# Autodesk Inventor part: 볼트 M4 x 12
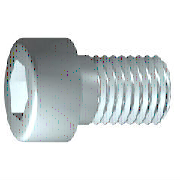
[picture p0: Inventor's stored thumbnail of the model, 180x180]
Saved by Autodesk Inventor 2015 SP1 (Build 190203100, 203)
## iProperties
IsCustomPart: 0
Created: 2012-02
Part Number: 볼트 M4 x 12
Material: 스테인리스강
Description: 6각 소켓 머리 캡 나사
Document SubType Name: Modeling
Standard: ISO 4762
Designer: mduedu
Standard Revision: Fourth edition 2004-03-01
Standards Organization: ISO
Language: ko-KR
Size Designation: M4 x 12
Categories: <MemberInstance><Categories><Category DisplayName="조임쇠" InternalName="e4da775c-781d-43d5-af7c-5136215cf5a6" Mnemonic="FSTN"><Category DisplayName="볼트" InternalN
Density: 8.08 g/cm^3
Appearance: 반광택
Author: mduedu
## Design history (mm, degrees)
sketch "스케치1"
  geometry: L1 (-1, 0)-(12, 0); L2 (12, 0)-(12, 2); L3 (12, 2)-(1.75, 2); L4 (1.75, 2)-(1.32, 2); L5 (1.32, 2)-(0, 2); L6 (0, 2)-(0, 3.5); L7 (0, 3.5)-(-4, 3.5); L8 (-4, 3.5)-(-4, 1.732); L9 (-4, 1.732)-(-2, 1.732); L10 (-2, 1.732)-(-1, 0); L11 (-7.2, 0)-(15.2, 0) reference; L12 (0, -0.7)-(0, 4.2) reference; L13 (1.75, 2)-(0, 2)
  constraints: 22 end point, 6 parallel, 2 collinear, 2 perpendicular, 1 horizontal, 1 point on line
  dimensions: "d1" = 10.25 distance from line of L3.end L2 (= GEL); "d2" = 0.42952 distance of L4.end L3.end (computed from GAL); "d3" = 4 distance between parallel lines of L8 L6 (= KOH); "d4" = 2 distance of L8.end L9.end (= INTI); "d5" = 60 deg angle of L10 L1; "d6" = 4 diameter of L3 L1 (= GD); "d7" = 4 diameter of L5 L1 (= BDM); "d8" = 3.4641 diameter of L9 L1 (= 1.1547 x SW); "d9" = 7 diameter of L7 L1 (= KOD); "d26" = 12 distance between parallel lines of L12 L2 (= NLG)
revolve "본체" sketch "스케치1" stored, may be unused: angle "d10" = 90 deg
sketch "스케치2"
  geometry: L1 (0, -4.9)-(0, 4.9) reference; L2 (-4.9, 0)-(4.9, 0) reference; L3 (1.732, 0)-(0.866, -1.5); L4 (0.866, -1.5)-(-0.866, -1.5); L5 (-0.866, -1.5)-(-1.732, 0); L6 (-1.732, 0)-(-0.866, 1.5); L7 (-0.866, 1.5)-(0.866, 1.5); L8 (0.866, 1.5)-(1.732, 0); 2 further points
  constraints: 12 end point, 1 coincident, 1 horizontal alignment, 1 point on line, 12 other
extrude "슬롯" join sketch "스케치2" stored distance "d11" = 10; taper "d12" = 0 deg
workplane "Work Plane1"
fillet "Fillet2" dims "d30" = 0.1 (= R)
body "Solid1"
fillet "모깎기1" dims "d17" = 0.4 (= RR)
feature "스레드" dims "d13" = 10.25 (= GEL), "d14" = 0
chamfer "모따기1" distance "d15" = 0.42941 (= -0.5 x SPD + 0.5 x GD); stored, may be unused: second distance "d16" = 0.42941 (= GUL), angle "d27" = 45 deg
other parameters: "GD" = 4 [user parameter; used in 2 equation terms], "NLG" = 12 [user parameter; used in 1 equation term], "GEL" = 10.25 [user parameter; used in 2 equation terms], "KOD" = 7 [user parameter; used in 1 equation term], "KOH" = 4 [user parameter; used in 1 equation term], "INTI" = 2 [user parameter; used in 1 equation term], "GAL" = 0.42941 (= 0.61345 x PTC) [user parameter; used in 1 equation term], "GUL" = 0.42941 (= 0.61345 x PTC) [user parameter; used in 1 equation term], "BDM" = 4 (= NND) [user parameter; used in 1 equation term], "SW" = 3 [user parameter; used in 2 equation terms], "RR" = 0.4 [user parameter; used in 1 equation term], "SPD" = 3.14117 (= NND - 1.2269 x PTC) [user parameter; used in 1 equation term], "d19" = 0, "d28" = 0, "d29" = 0, "R" = 0.1 [user parameter; used in 1 equation term], "TOA" = 30 deg [user parameter], "GD1" = 3.14117 (= THREADDIA - 1.2269 x PTC) [user parameter], "THREADDIA" = 4 [user parameter; used in 1 equation term], "FAWI" = 45 deg [user parameter], "TPU" = 14.28571 (computed from PTC) [user parameter], "PTC" = 0.7 [user parameter; used in 5 equation terms], "NND" = 4 [user parameter; used in 2 equation terms], "E0" = 3.465 (= 1.155 x SW) [user parameter]
